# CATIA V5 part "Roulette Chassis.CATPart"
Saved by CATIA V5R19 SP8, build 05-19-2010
Part number: Roulette Chassis
Nomenclature: 56
Material "Plastique": density 1200 kg/m3, Young's modulus 2.2e+09 Pa, Poisson ratio 0.38, thermal expansion 6.84e-05 1/K
Bounding box of the stored display mesh (mm): x -27.494 to 27.494, y -27.5 to 27.5, z -12.8 to 12.8
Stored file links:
  C:\Users\rphgr\Desktop\0_Tapis_TC520B_vitesse\Roulette Chassis.CATPart
  D:\Programmes\DassaultSysteme\win_b64\startup\materials\French\Catalog.CATMaterial
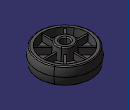
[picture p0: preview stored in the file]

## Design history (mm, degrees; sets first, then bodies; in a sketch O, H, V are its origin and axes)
AxisSystem1: origin (0, 0, 0), X (1, 0, 0), Y (0, 1, 0), Z (0, 0, 1)
Body1 (main body), material "Plastique"
  Sketch1 on ZX plane of AxisSystem1, origin (0, 0, 0), H (0, 0, 1), V (1, 0, 0)
    axis line L1 (-113.3355, 0) -> (280.5209, 0)
    point P1 (-113.3355, 0)
    line L2 (-12.8, 4.2) -> (-12.8, 8.7)
    line L3 (-12.8, 8.7) -> (-0.8, 8.7)
    line L4 (-0.8, 8.7) -> (-0.8, 22.8)
    line L5 (-0.8, 22.8) -> (-8.4, 22.8)
    line L6 (-8.4, 22.8) -> (-8.4, 26)
    point P7 (-8.4, 26)
    arc A1 centre (0, 3.23) radius 24.27 from (0, 27.5) to (-8.4, 26) ccw
    point P8 (0, 3.23)
    line L7 (-12.8, 4.2) -> (0, 4.2)
    point P9 (0, 4.2)
    point P10 (0, 27.5)
    reference intersected line E1 through (0, 0) direction (0, 1) from XY plane of AxisSystem1
    reference intersected line E2 through (0, 0) direction (0, 1) from XY plane of AxisSystem1
    point P12 (0, 0)
    line L8 (0, 27.5) -> (0, 4.2)
    distance L7 L1 = 4.2
    distance L2 E1 = 12.8
    distance L2 L4 = 12
    distance L6 E2 = 8.4
    "Radius" L3 L1 = 8.7
    "Radius" L5 L1 = 22.8
    "Radius" P7 L1 = 26
    "Radius" L1 P10 = 27.5
    coincidence: P1 H, P8 V, P9 V, P10 V
    horizontal: L1 H, L3 H, L5 H, L7 H
    vertical: L2 V, L4 V, L6 V, L8 V
  Shaft1: profile Sketch1, axis Sketch1.L1, angle 360
  Draft1: PullDir (0, 0, 1), Angle -5, SupportToDraft face of Shaft1 from Sketch1.L3, Neutral face of Shaft1 from Sketch1.L2
  Draft2: PullDir (0, 0, 1), Angle -5, SupportToDraft face of Shaft1 from Sketch1.L5, Neutral face of Shaft1 from Sketch1.L6
  Fillet1: radius 1, on face of Shaft1 from Sketch1.L2; edge [face of Shaft1 from Sketch1.L6 | face of Shaft1 from Sketch1.A1]
  Plane1: type Offset, RefPlane face of Shaft1 from Sketch1.L6, Offset 1.3
  Sketch2 on Plane1, origin (0, 0, -7.1), H (1, 0, 0), V (0, -1, 0)
    line L1 (0, 23.043) -> (0, 7.1908)
    point P1 (0, 23.043)
    coincidence: P1 V
    vertical: L1 V
  Stiffener1: ThicknessValue 1.75, ExtendedProfile Sketch2, ThicknessTop 0
  CircPattern1: of Stiffener1, instances 8, angular step 45 {= 360.0*1 deg/CircPattern1.AngularNumber}, axis from face of Shaft1 from Sketch1.L7
  Mirror1: of the body so far, about face of Shaft1 from Sketch1.L8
